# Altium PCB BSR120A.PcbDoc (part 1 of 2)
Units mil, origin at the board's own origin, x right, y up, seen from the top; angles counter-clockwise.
Board outline 3250 x 2500 mil, 4 copper layers (Top Layer, MidLayer1, MidLayer2, Bottom Layer), stack 61.2 mil thick; 56 components, 15 nets, 102 pads, 73 vias.
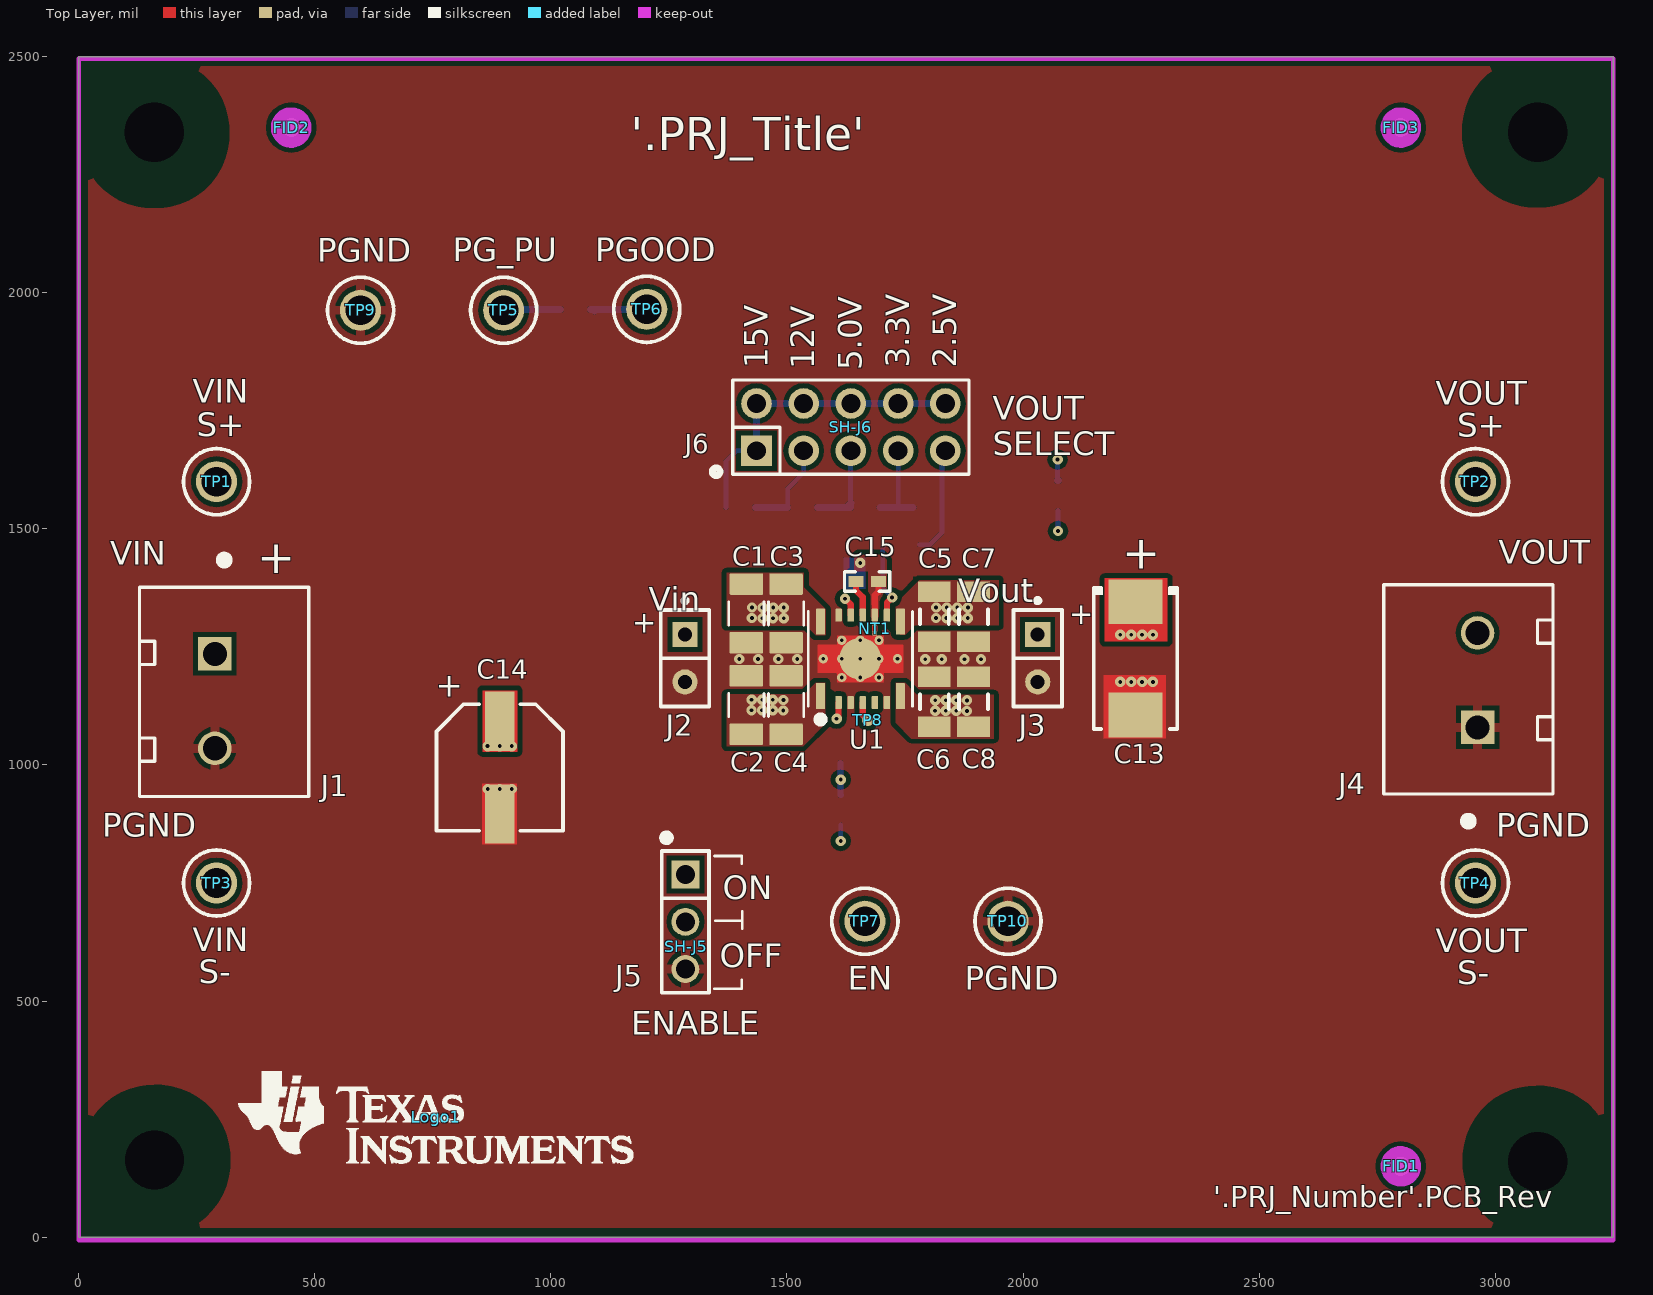
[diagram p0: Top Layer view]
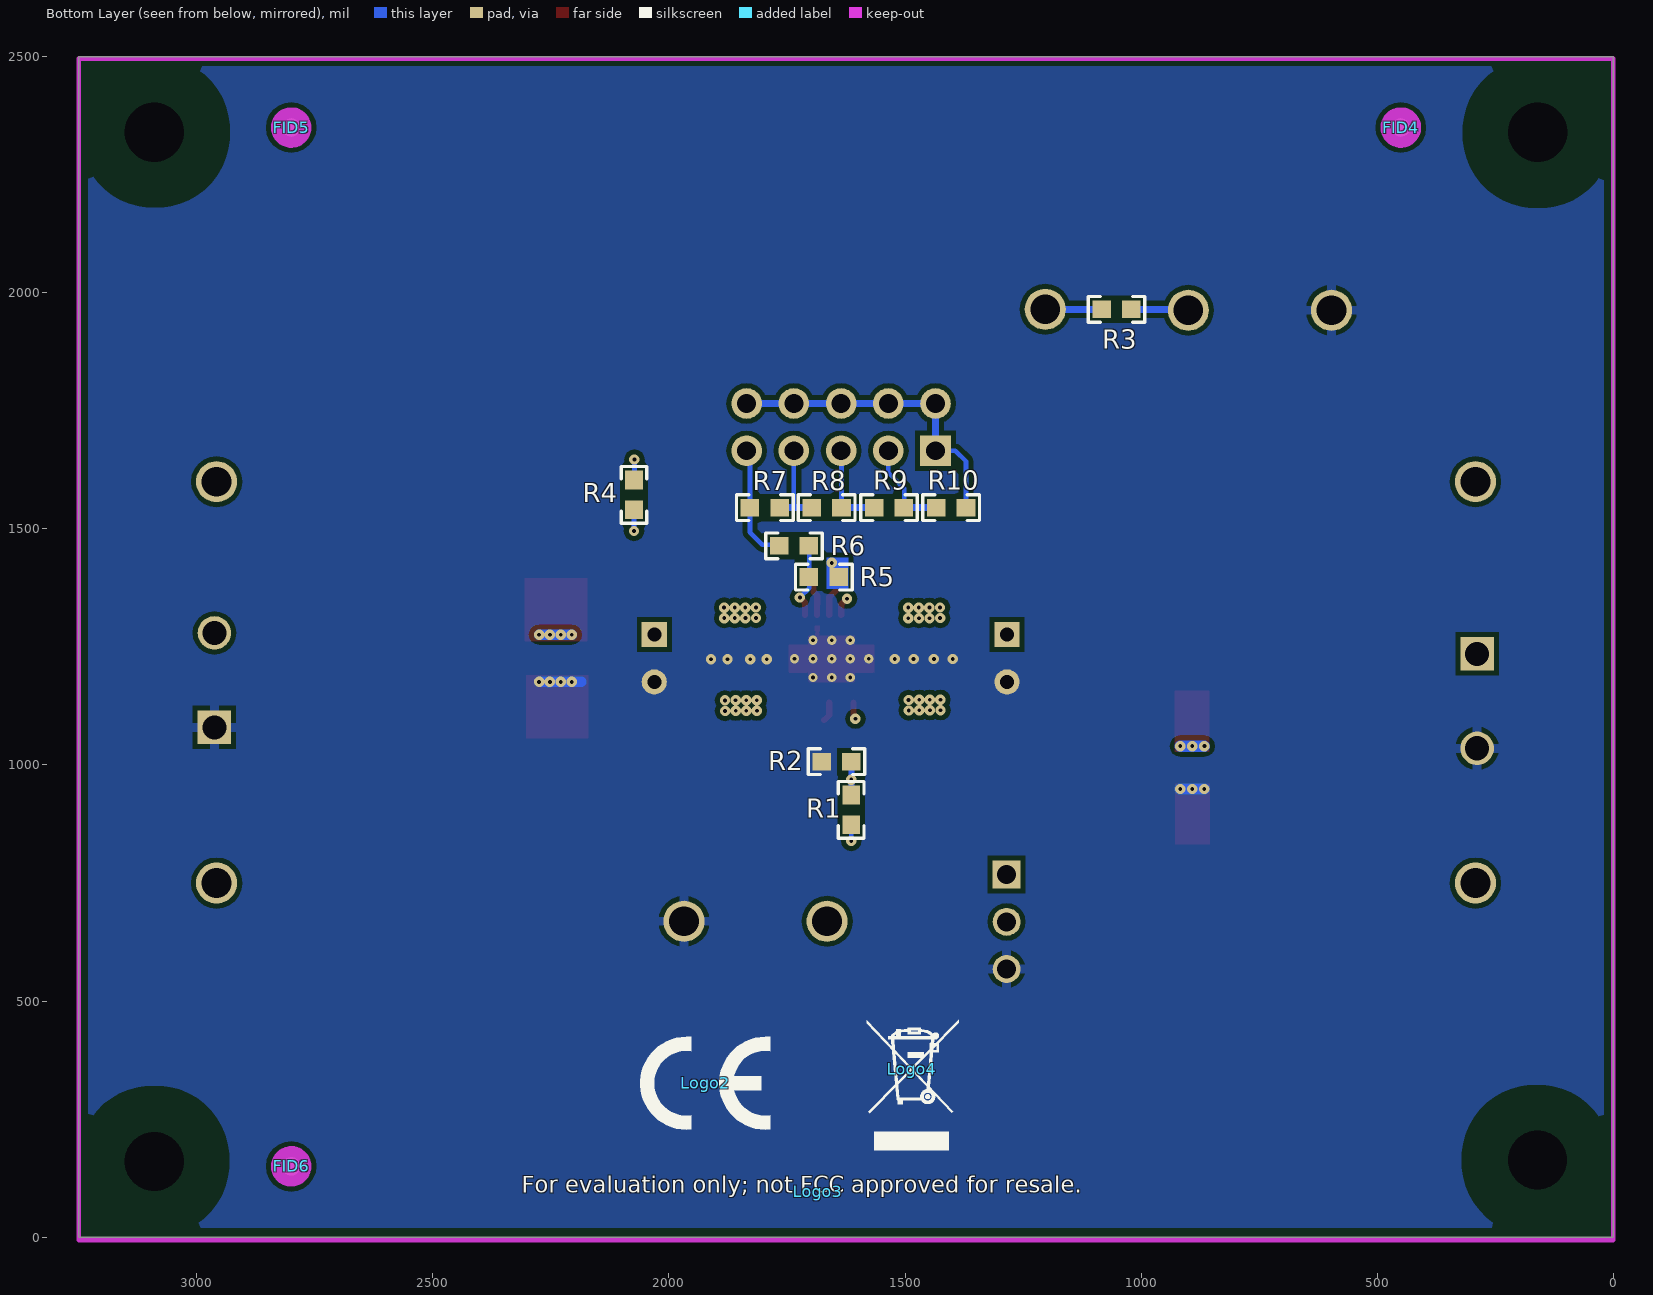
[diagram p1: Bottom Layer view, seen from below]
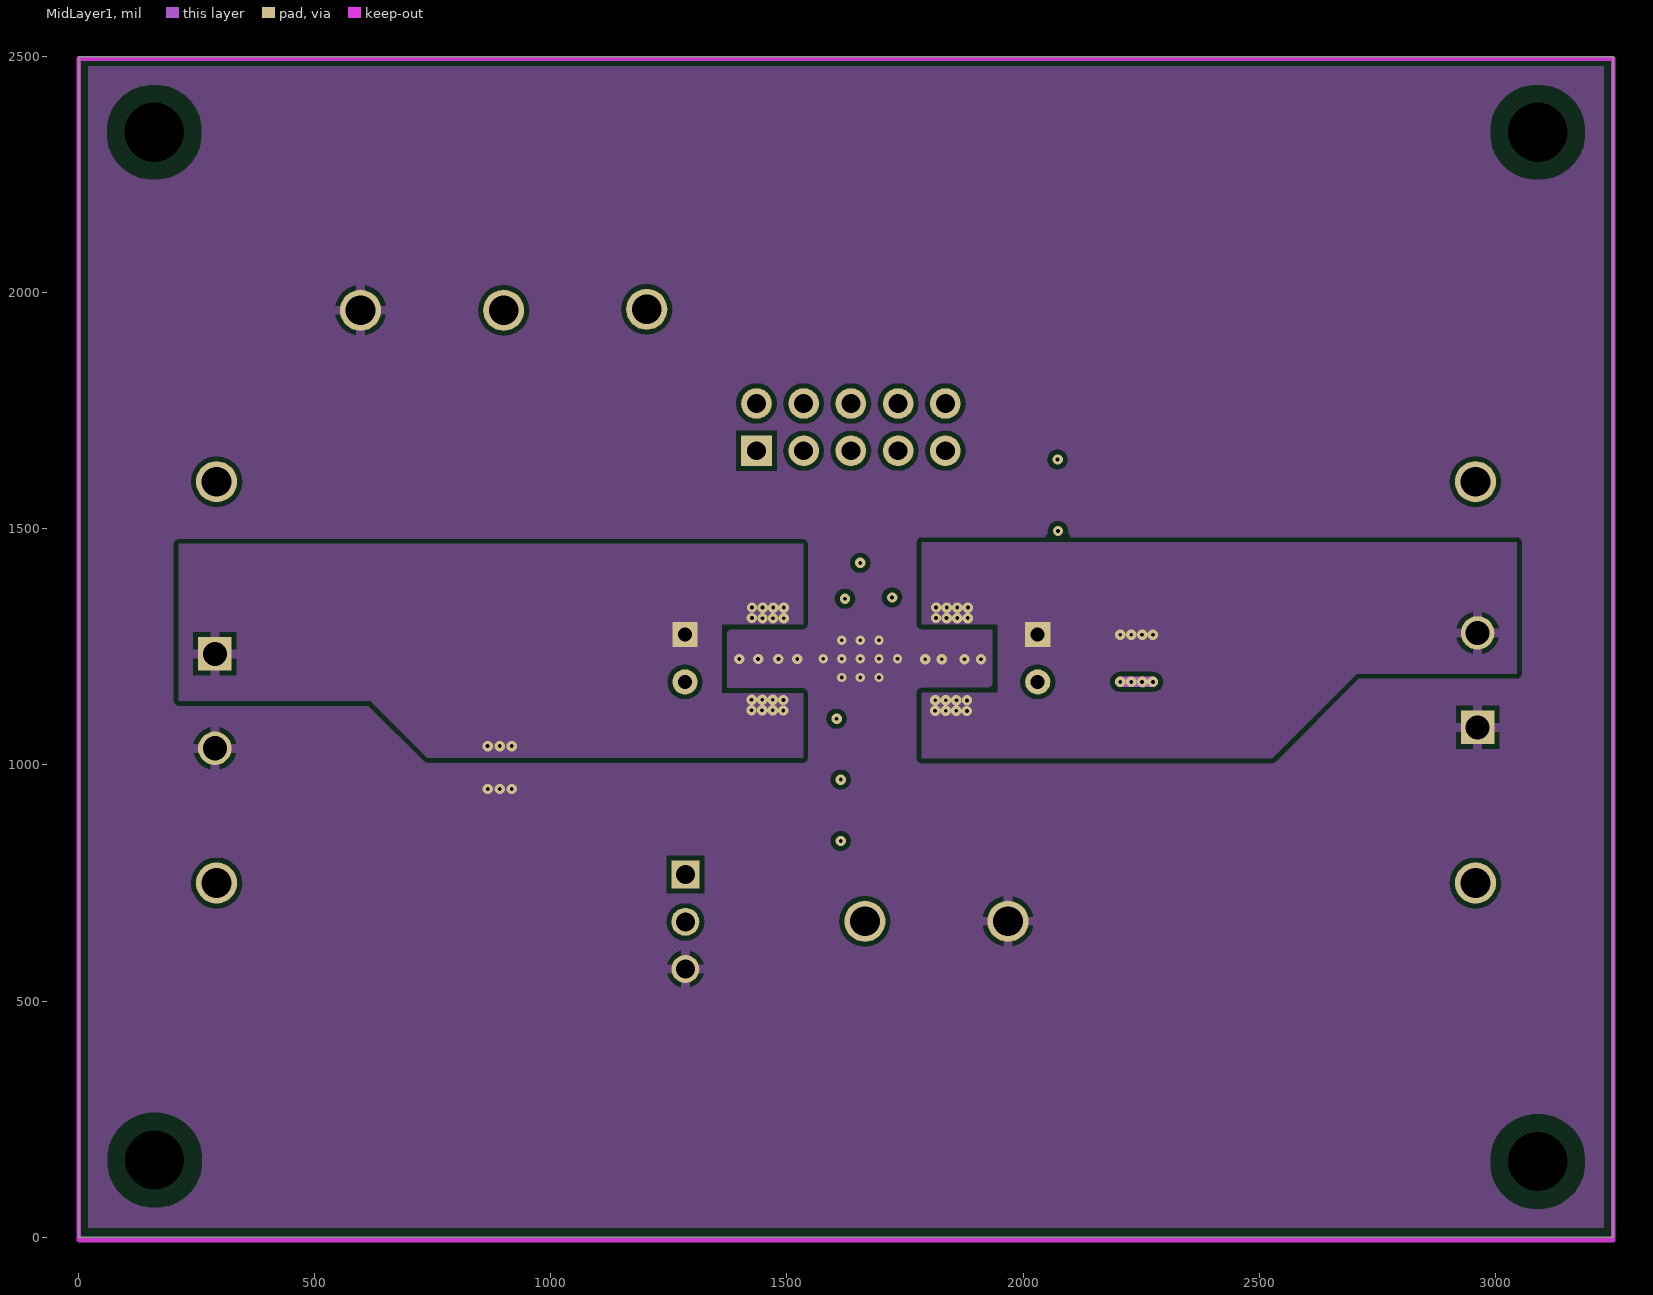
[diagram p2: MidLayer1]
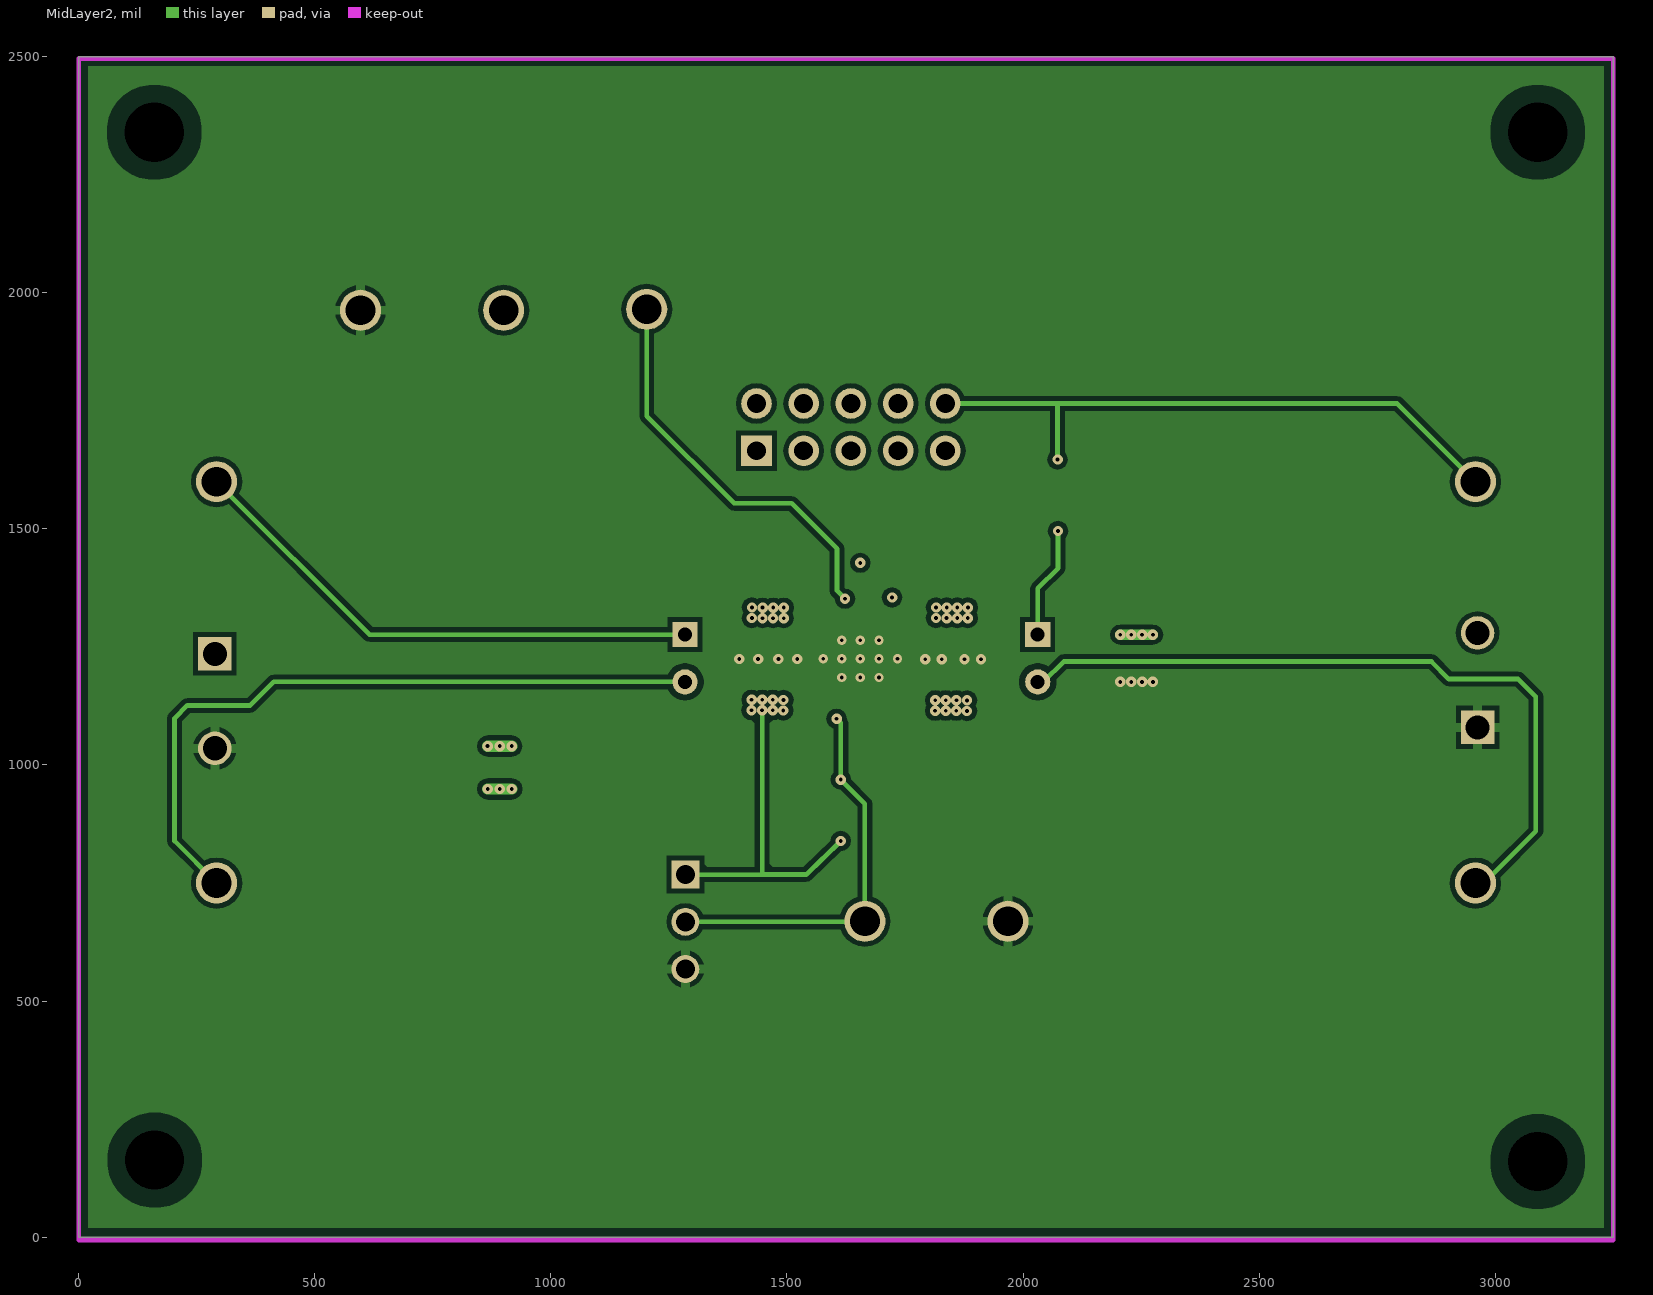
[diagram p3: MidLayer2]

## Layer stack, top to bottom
Top Solder: solder mask 0.4, Solder Resist, Dk 3.5
Top Layer: signal copper 2.8
Dielectric1: prepreg 5, FR-4 High Tg, Dk 4.2
MidLayer1: signal copper 2.8
Dielectric2: core 40, FR-4 High Tg, Dk 4.2
MidLayer2: signal copper 2.8
Dielectric3: prepreg 5, FR-4 High Tg, Dk 4.2
Bottom Layer: signal copper 2.8
Bottom Solder: solder mask 0.4, Solder Resist, Dk 3.5

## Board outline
0,0 0,2500 3250,2500 3250,0

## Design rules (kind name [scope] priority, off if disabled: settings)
AcuteAngle [All] p1: minimum=4.50000000000000E+0001 checktracksonly=TRUE
AssemblyTestPointUsage [All] p1: valid=2
BoardOutlineClearance BoardOutlineClearance_MountingHoles [OnCopper and InComponentClass('Mounting Holes')] p1: gap=40 ignorepadtopadclearanceinfootprint=FALSE
BoardOutlineClearance BoardOutlineClearance_Poly [OnCopper and IsPoly] p2: gap=20 ignorepadtopadclearanceinfootprint=FALSE
BoardOutlineClearance [OnCopper and Not InComponentClass('Logo') and not InComponentClass('FiducialMark') and not InRegion(1000,500,4000,800) and not InPoly] p3: gap=20 ignorepadtopadclearanceinfootprint=FALSE
Clearance Clearance_Keepouts [((IsTrack Or IsArc) And Not InPoly) And IsFree and IsKeepOut vs ((IsTrack Or IsArc) And Not InPoly) And IsFree and IsKeepOut] p1: gap=0 ignorepadtopadclearanceinfootprint=FALSE
Clearance Clearance_Poly [InPolygon] p2: gap=10 ignorepadtopadclearanceinfootprint=FALSE except(0: Arc-Hole Track-Hole SMDPad-Hole THPad-Hole Via-Hole Fill-Hole Poly-Hole Region-Hole Text-Hole)
Clearance Clearance_FiducialMark [IsKeepOut and InComponentClass('FiducialMark') vs IsPad and InComponentClass('FiducialMark')] p3: gap=0 ignorepadtopadclearanceinfootprint=FALSE
Clearance [All] p4: gap=10 ignorepadtopadclearanceinfootprint=FALSE except(0: Arc-Hole Track-Hole SMDPad-Hole THPad-Hole Via-Hole Fill-Hole Poly-Hole Region-Hole Text-Hole)
ComponentClearance ComponentClearance_MountingHoles_FiducialMarks [InComponentClass('Mounting Holes') vs InComponentClass('FiducialMark')] p1: gap=10 collisioncheckmode=3 verticalgap=10 showdistances=FALSE
ComponentClearance ComponentClearance_Shunt [InComponentClass('Header') vs InComponentClass('Shunt')] p2: gap=0 collisioncheckmode=3 verticalgap=0 showdistances=FALSE
ComponentClearance ComponentClearance_Logo [InComponentClass('Logo')] p3: gap=10 collisioncheckmode=3 verticalgap=10 showdistances=FALSE
ComponentClearance ComponentClearance_ScrewToNut [(HasFootprint('NY PMS 440 0025 PH')) vs (HasFootprint('Keystone_1902C'))] p4: gap=5 collisioncheckmode=3 verticalgap=10 showdistances=FALSE
ComponentClearance ComponentClearance_MountingHoles [InComponentClass('Mounting Holes')] p5: gap=10 collisioncheckmode=3 verticalgap=100000 showdistances=FALSE
ComponentClearance ComponentClearance_SmallPassives [HasFootprint('0201*') or HasFootprint('0402*') or HasFootprint('0508') or HasFootprint('0603*') or HasFootprint('0612') or HasFootprint('0805*') or HasFootprint('0815*') or HasFootprint('0830*') or HasFootprint('1206*') or HasFootprint('1210*') or HasFootprint('1808*') or HasFootprint('1812*') or HasFootprint('1825*') or HasFootprint('2010*') or HasFootprint('2220*') or HasFootprint('2225*') or HasFootprint('2512*') or HasFootprint('2728*') or HasFootprint('3518*') vs HasFootprint('0201*') or HasFootprint('0402*') or HasFootprint('0508') or HasFootprint('0603*') or HasFootprint('0612') or HasFootprint('0805*') or HasFootprint('0815*') or HasFootprint('0830*') or HasFootprint('1206*') or HasFootprint('1210*') or HasFootprint('1808*') or HasFootprint('1812*') or HasFootprint('1825*') or HasFootprint('2010*') or HasFootprint('2220*') or HasFootprint('2225*') or HasFootprint('2512*') or HasFootprint('2728*') or HasFootprint('3518*')] p6: gap=8 collisioncheckmode=3 verticalgap=8 showdistances=FALSE
ComponentClearance ComponentClearance_THtoSMT [IsThruComponent vs IsSMTComponent] p7: gap=10 collisioncheckmode=3 verticalgap=30 showdistances=FALSE
ComponentClearance ComponentClearance_THtoTH [IsThruComponent vs IsThruComponent] p8: gap=10 collisioncheckmode=3 verticalgap=30 showdistances=FALSE
ComponentClearance "ComponentClearance_U1 to NT1" [InComponent('NT1') vs InComponent('U1')] p9: gap=0 collisioncheckmode=3 verticalgap=0 showdistances=FALSE
ComponentClearance [All] p10: gap=10 collisioncheckmode=3 verticalgap=30 showdistances=FALSE
DiffPairsRouting [All] p1: maxlimit=100 minlimit=10 mostfreqgap=10 toplayer_minwidth=15 toplayer_maxwidth=15 toplayer_prefwidth=15 midlayer1_minwidth=15 midlayer1_maxwidth=15 midlayer1_prefwidth=15 midlayer2_minwidth=15 midlayer2_maxwidth=15 midlayer2_prefwidth=15 bottomlayer_minwidth=15 bottomlayer_maxwidth=15 bottomlayer_prefwidth=15 maxuncoupledlength=1000
FabricationTestPointUsage TestPointUsage [All] p1: valid=2 allowmultiple=FALSE
FabricationTestpoint Testpoint [All] p1: side=3 testpointundercomponent=TRUE minsize=40 maxsize=100 preferedsize=60 minholesize=0 maxholesize=40 preferedholesize=32 testpointgrid=1 allowsidetop=TRUE allowsidebottom=TRUE usegrid=TRUE gridtolerance=0.01
FanoutControl Fanout_LCC [IsLCC] p1: bgadir=Out bgaviamode=Centered fanoutstyle=Auto fanoutdirection=Alternating viagrid=1 // Fanout_LCC (Default Rule)
FanoutControl Fanout_BGA [IsBGA] p2: bgadir=Out bgaviamode=Centered fanoutstyle=Auto fanoutdirection=Alternating viagrid=1 // Fanout_BGA (Default Rule)
FanoutControl Fanout_Default [All] p4: bgadir=Out bgaviamode=Centered fanoutstyle=Auto fanoutdirection=Alternating viagrid=1 // Fanout_Default (Default Rule)
FanoutControl Fanout_Small [(CompPinCount < 5)] p5: bgadir=Out bgaviamode=Centered fanoutstyle=Auto fanoutdirection=OutThenIn viagrid=1 // Fanout_Small (Default Rule)
Height [All] p1: minheight=0 maxheight=10000 prefheight=500
HoleSize [All] p1: absolutevalues=TRUE maxlimit=251 minlimit=6 maxpercent=80.000 minpercent=20.000
MinimumAnnularRing MinimumAnnularRing_ThermalPadVias [IsVia and InAnyComponent] p1: minimumring=5
MinimumAnnularRing [All] p2: minimumring=5
MinimumSolderMaskSliver MinimumSolderMaskSliver_1 [HasFootprint('RDA0015A-MFG') vs (InComponent('U1') AND IsVia)] p1: minsoldermaskwidth=1
MinimumSolderMaskSliver MinimumSolderMaskSliver_Logo [InComponentClass('Logo') vs InComponentClass('Logo')] p2: minsoldermaskwidth=0.7
MinimumSolderMaskSliver [All] p3: minsoldermaskwidth=3.94
PlaneClearance PlaneClearance_1 [OnLayer('Top Layer')] p1: clearance=7.87
PlaneClearance [All] p2: clearance=9.84
PlaneConnect PlaneConnect_via [IsVia] p1: planeconnectstyle=Direct reliefexpansion=20 reliefentries=4 reliefconductorwidth=10 reliefairgap=10
PlaneConnect [All] p2: planeconnectstyle=Relief reliefexpansion=10 reliefentries=4 reliefconductorwidth=10 reliefairgap=10
PolygonConnect PolygonConnect_ESD120 [HasFootprint('On-Shore_ED120_2DS')] p1: connectstyle=Relief reliefconductorwidth=25 reliefentries=4 polygonreliefangle="90 Angle" airgapwidth=10
PolygonConnect PolygonConnect_tp [(InComponent('TP*') and not (InComponent('TP9') or InComponent('TP10')))] p2: connectstyle=NoConnect reliefconductorwidth=25 reliefentries=4 polygonreliefangle="90 Angle" airgapwidth=10
PolygonConnect PolygonConnect_logo [InComponent('Logo1')] p3: connectstyle=Direct reliefconductorwidth=10 reliefentries=4 polygonreliefangle="90 Angle" airgapwidth=10
PolygonConnect PolygonConnect_Via [IsVia] p4: connectstyle=Direct reliefconductorwidth=10 reliefentries=4 polygonreliefangle="90 Angle" airgapwidth=10
PolygonConnect PolygonConnect_1 [IsThruPin AND NOT (InComponent('J3') or InComponent('J2'))] p5: connectstyle=Relief reliefconductorwidth=20 reliefentries=4 polygonreliefangle="90 Angle" airgapwidth=10
PolygonConnect PolygonConnect_poly [IsPoly] p6: connectstyle=Direct reliefconductorwidth=10 reliefentries=4 polygonreliefangle="90 Angle" airgapwidth=8
PolygonConnect [All] p7: connectstyle=Relief reliefconductorwidth=10 reliefentries=4 polygonreliefangle="90 Angle" airgapwidth=8
RoutingVias ThermalPadVias [IsVia and InAnyComponent] p1: holewidth=7.87 width=19.68 viastyle="Through Hole" minholewidth=7.87 minwidth=19.68 maxholewidth=12.99 maxwidth=23.62
RoutingVias [All] p2: holewidth=16 width=34 viastyle="Through Hole" minholewidth=6 minwidth=19 maxholewidth=40 maxwidth=65
SilkToBoardRegionClearance SilkToBoardRegionClearance_1 [All] p1:
SilkToSilkClearance SilkToSilkClearance_Pb-FreeLogo [(HasFootprint('Pb-Free_Overlay_Medium') OR HasFootprint('Pb-Free_Overlay_Small')) vs (HasFootprint('Pb-Free_Overlay_Medium') OR HasFootprint('Pb-Free_Overlay_Small'))] p1: silktosilkclearance=0
SilkToSilkClearance [All] p2: silktosilkclearance=3
SilkToSolderMaskClearance "Cap silkscreen on vias" [IsTrack and (InComponent('C1') or InComponent('C11') or InComponent('C12') or InComponent('C2')or InComponent('C5') or InComponent('C6') or InComponent('C7') or InComponent('C8') or InComponent('C13') or InComponent('C14') or InComponent('C15') or InComponent('C16') or InComponent('C11') or InComponent('C12') or InComponent('C3') or InComponent('C4') or InComponent('R1') or InComponent('R2') or InComponent('U1')) vs IsVia] p1: minsilkscreentomaskgap=0 clearancetoexposedcopper=FALSE
SilkToSolderMaskClearance SilkToComponentPadClearance [(IsPad or IsFill or IsRegion) and InAnycomponent] p2: minsilkscreentomaskgap=4.8 clearancetoexposedcopper=TRUE
SilkToSolderMaskClearance "Silk to Solder Mask Opening" [All] p3: minsilkscreentomaskgap=4 clearancetoexposedcopper=FALSE
SolderMaskExpansion [All] p1: expansion=1.97
Width [All] p1: maxlimit=100 minlimit=6 preferedwidth=10 checkconnectedcopper=TRUE
13 further rules are at their usual default settings.

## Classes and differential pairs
component class Shunt: SH-J5 SH-J6
component class Header: J5 J6
component class AssemblyNote: ZZ1 ZZ2 ZZ3 ZZ4 ZZ5
component class FiducialMark: FID1 FID2 FID3 FID4 FID5 FID6
component class Logo: Logo1
component class BSR120A_Hardware: !PCB FID1 FID2 FID3 FID4 FID5 FID6 Logo1 Logo2 Logo3 Logo4 SH-J5 SH-J6 ZZ1 ZZ2 ZZ3 ZZ4 ZZ5
component class BSR120A: C1 C2 C3 C4 C5 C6 C7 C8 C13 C14 C15 J1 J2 J3 J4 J5 J6 NT1 R1 R2 R3 R4 R5 R6 R7 R8 R9 R10 TP1 TP2 TP3 TP4 TP5 TP6 TP7 TP8 TP9 TP10 U1

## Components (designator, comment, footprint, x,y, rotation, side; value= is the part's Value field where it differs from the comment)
C1 "GRM31CC72A475KE11L" FP-GRM31CC72A475KE11L_1206-MFG 1414,1321 r90 top value=4.7µF
C2 "GRM31CC72A475KE11L" FP-GRM31CC72A475KE11L_1206-MFG 1414,1127 r270 top value=4.7µF
C3 "GRM31CC72A475KE11L" FP-GRM31CC72A475KE11L_1206-MFG 1498,1321 r90 top value=4.7µF
C4 "GRM31CC72A475KE11L" FP-GRM31CC72A475KE11L_1206-MFG 1498,1127 r270 top value=4.7µF
C5 "C3216X5R1E476M160AC" 1206_190L 1812,1314 r90 top value=47uF
C6 "C3216X5R1E476M160AC" 1206_190L 1812,1134 r270 top value=47uF
C7 "C3216X5R1E476M160AC" 1206_190L 1895,1314 r90 top value=47uF
C8 "C3216X5R1E476M160AC" 1206_190L 1895,1134 r270 top value=47uF
C13 "T520Y337M010ATE035" 7343-40 2238,1226 r270 top value=330uF
C14 "EEEFT1H470AP" Panasonic_D 891.6,994.6 r270 top value=47uF
C15 "EMK105BJ105KVHF" 0402 1669.92,1388.48 r0 top value=1uF
FID1 "Fiducial" Fiducial10-20 2800,150 r0 top
FID2 "Fiducial" Fiducial10-20 450,2350 r0 top
FID3 "Fiducial" Fiducial10-20 2800,2350 r0 top
FID4 "Fiducial" Fiducial10-20 450,2350 r180 bottom
FID5 "Fiducial" Fiducial10-20 2800,2350 r180 bottom
FID6 "Fiducial" Fiducial10-20 2800,150 r180 bottom
J1 "OSTTA024163" On-Shore_OSTTA024163 308,1155 r270 top
J2 "310-43-102-41-001000" Mill-max_310-43-102-41-001000 1284,1226 r270 top
J3 "310-43-102-41-001000" Mill-max_310-43-102-41-001000 2031,1226 r270 top
J4 "OSTTA024163" On-Shore_OSTTA024163 2943,1160 r90 top
J5 "PEC03SAAN" CONN_PEC03SAAN 1284.74,667.8 r270 top
J6 "PEC05DAAN" CONN_PEC05DAAN 1635.4,1715.5 r0 top
Logo1 "Texas Instruments" TI_Stacked_Overlay_Small 756.39,253.53 r0 top
Logo2 "CE Mark" CE_Mark_5mm 1923,326 r180 bottom
Logo3 "FCC disclaimer" FCC_disclaimer 1685,96 r180 bottom
Logo4 "WEEE logo" WEEE_Minimum 1486,356 r180 bottom
NT1 "Net-Tie" Net-Tie_10mil 1686,1289 r270 top net-tie
R1 "CRCW0603402KFKEA" 0603 1614,905 r270 bottom value=402k
R2 "CRCW0603133KFKEA" 0603 1645,1007 r180 bottom value=133k
R3 "CRCW060349K9FKEA" 0603 1052,1965 r0 bottom value=49.9k
R4 "CRCW060320R0JNEA" 0603 2074,1572 r90 bottom value=20
R5 "CRCW060310K0FKEA" 0603 1672,1398 r0 bottom value=10.0k
R6 "CRCW060315K0FKEA" 0603 1735,1464 r0 bottom value=15.0k
R7 "CRCW06038K06FKEA" 0603 1797,1545 r180 bottom value=8.06k
R8 "CRCW060316K9FKEA" 0603 1666,1545 r180 bottom value=16.9k
R9 "CRCW060369K8FKEA" 0603 1534,1545 r180 bottom value=69.8k
R10 "CRCW060330K1FKEA" 0603 1402.4,1545 r180 bottom value=30.1k
SH-J5 "2SN-BK-G" 2SN-BK-G 1287,615 r90 top value=1x2
SH-J6 "2SN-BK-G" 2SN-BK-G 1635.4,1715.5 r90 top value=1x2
TP1 "5010" Keystone5010 292,1600 r90 top
TP2 "5010" Keystone5010 2958,1600 r90 top
TP3 "5011" Keystone5011 292,750 r90 top
TP4 "5011" Keystone5011 2958,750 r90 top
TP5 "5012" Keystone5012 900,1963 r0 top
TP6 "5012" Keystone5012 1203,1965 r0 top
TP7 "5012" Keystone5012 1665,669 r0 top
TP8 "TESTPOINT" TP_25MIL-SMT 1671,1095 r0 top
TP9 "5011" Keystone5011 597,1963 r180 top
TP10 "5011" Keystone5011 1968,669 r0 top
U1 "TPSM5601R5H" RDA0015A-MFG 1655.45,1224.74 r90 top
ZZ1 "These assemblies are ESD sensitive, ESD precautions shall be observed." AssemblyNote -430,3004 r0 top
ZZ2 "These assemblies must be clean and free from flux and all contaminants. Use of no clean flux is not acceptable." AssemblyNote -430,3188 r0 top
ZZ3 "These assemblies must comply with workmanship standards IPC-A-610 Class 2, unless otherwise specified." AssemblyNote -430,3371 r0 top
ZZ4 "Place SH-J5 on J5 pins 2 and 3" AssemblyNote -425,3544 r0 top
ZZ5 "Place SH-J6 on J6 pins 5 and 6" AssemblyNote -434,3678 r0 top

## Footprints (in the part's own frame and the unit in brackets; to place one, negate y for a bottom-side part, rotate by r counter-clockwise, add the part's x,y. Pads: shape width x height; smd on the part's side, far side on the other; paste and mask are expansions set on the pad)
2SN-BK-G [mil] "Samtec STEP model"
  round 1 on Mech3: 0(0,0)
  body extent -78,-39 79,39, height 188
0402 [mm] "0402 from SM-752 data"
  rect 0.8x0.6 smd: 1(-0.6,0) 2(0.6,0)
  silkscreen extent -1.22,-0.52 1.22,0.52, body extent -0.55,-0.3 0.55,0.3, height 0.6
0603 [mm] "0603 from SM-752 data"
  rect 1x0.95 smd: 1(-0.8,0) 2(0.8,0)
  silkscreen extent -1.52,-0.69 1.52,0.69, body extent -0.87,-0.47 0.87,0.47, height 1
1206_190L [mm] "1206_190"
  rect 1.1x1.75 smd: 1(-1.35,0) 2(1.35,0)
  silkscreen extent -0.4,-0.77 0.4,0.77, body extent -1.75,-0.95 1.75,0.95, height 1.9
7343-40 [mm] "Molded, 2-Leads, Body 7.3x4.3mm, Height 4mm"
  rect 2.4x2.9 smd: 1(-3.05,0) 2(3.05,0)
  silkscreen extent -3.8,-2.25 3.8,2.25, body extent -3.8,-2.25 3.8,2.25, height 4.01
AssemblyNote [mil] "Assembly Note"
CE_Mark_5mm [mil] "Minimum text height for CE Mark"
  silkscreen extent -138,-98 138,98
CONN_PEC03SAAN [mm] "SULLINS"
  rect 1.5x1.5 hole 1.016: 1(-2.54,0)
  round 1.5 hole 1.016: 2(0,0) 3(2.54,0)
  silkscreen extent -4.72,-1.27 3.81,1.27, body extent -3.84,-1.3 3.84,1.3, height 8.38
CONN_PEC05DAAN [mm] "SULLINS"
  rect 1.65x1.65 hole 1.016 mask+0: 1(-5.08,-1.27)
  round 1.65 hole 1.016 mask+0: 2(-5.08,1.27) 3(-2.54,-1.27) 4(-2.54,1.27) 5(0,-1.27) 6(0,1.27) 7(2.54,-1.27) 8(2.54,1.27) 9(5.08,-1.27) 10(5.08,1.27)
  silkscreen extent -7.45,-2.6 6.35,2.54, body extent -6.35,-2.54 6.35,2.54, height 8.38
FCC_disclaimer [mil]
Fiducial10-20 [mm]
  round 1 smd mask+0.5: 1(0,0)
  Top Layer keep-out circle w1.178: c0,0 r0.5
FP-GRM31CC72A475KE11L_1206-MFG [mm]
  rrect9% 1.15x1.8 smd paste+0 mask+0: 1(-1.575,0) 2(1.575,0)
  silkscreen extent -0.63,-0.95 0.63,0.95, body extent -2.25,-1.05 2.25,1.05, height 0.25
Keystone5010 [mil] "Keystone Multipurpose loops"
  round 87 hole 63: 1(0,0)
  silkscreen extent -70,-70 70,70, body extent -63,-63 63,62, height 319
Keystone5011 [mil] "Keystone Multipurpose loops"
  round 87 hole 63: 1(0,0)
  silkscreen extent -70,-70 70,70, body extent -63,-63 63,62, height 319
Keystone5012 [mil] "Keystone Multipurpose loops"
  round 87 hole 63: 1(0,0)
  silkscreen extent -70,-70 70,70, body extent -63,-63 63,62, height 319
Mill-max_310-43-102-41-001000 [mm] "Mill-max"
  rect 1.35x1.35 hole 0.75: 1(-1.27,0)
  round 1.35 hole 0.75: 2(1.27,0)
  silkscreen extent -3.22,-1.3 2.6,1.3, body extent -2.55,-1.27 2.55,1.27, height 4.22
Net-Tie_10mil [mil] "10mil net tie, no solder mask opening, no solder paste"
  rect 10x10 smd paste-5 mask-5: 1(-10,0) 2(10,0)
  Top Layer region: -6,5 6,5 6,-5 -6,-5
On-Shore_OSTTA024163 [mm] "TERM BLOCK 2x1, 5.08mm, TH"
  rect 1.8x1.8 hole 1.3: 1(-2.04,-0.5)
  round 1.8 hole 1.3 paste+0: 2(3.04,-0.5)
  silkscreen extent -7.18,-4.55 5.63,4.55, body extent -5.68,-4.6 5.68,4.6, height 13
Panasonic_D [mm] "SMD, 2-Leads, Dia 6.3mm"
  rect 3.2x1.6 smd: 1(-2.5,0) 2(2.5,0)
  silkscreen extent -3.4,-3.4 3.4,3.4, body extent -3.4,-3.4 3.4,3.4, height 6.11
RDA0015A-MFG [mm]
  rrect20% 1.4x0.5 smd paste-1000 mask+0: 1(-2,2.145) 7(-2,-2.155) 8(2,-2.155) 14(2,2.145)
  rrect29% 0.7x0.35 smd paste-1000 mask+0: 2(-2.35,1.17) 3(-2.35,0.52) 4(-2.35,-0.13) 5(-2.35,-0.78) 6(-2.35,-1.43) 9(2.35,-1.43) 10(2.35,-0.78) 11(2.35,-0.13) 12(2.35,0.52) 13(2.35,1.17)
  round 2.25 smd paste-1000 mask+0: 15(0,0)
  Top Layer region: -0.7,2.3 -0.725,2.293 -0.743,2.275 -0.75,2.25 -0.75,2.25 -0.75,1.3 -0.754,1.281 -0.765,1.265 -0.781,1.254 -0.8,1.25 -0.8,1.25 -1.2,1.25 -1.225,1.243 -1.243,1.225 -1.25,1.2 -1.25,1.2 -1.25,-1.2 -1.243,-1.225 -1.225,-1.243 -1.2,-1.25 -1.2,-1.25 -0.8,-1.25 -0.781,-1.254 -0.765,-1.265 -0.754,-1.281 -0.75,-1.3 -0.75,-1.3 -0.75,-2.25 -0.743,-2.275 -0.725,-2.293 -0.7,-2.3 -0.7,-2.3 0.7,-2.3 0.725,-2.293 0.743,-2.275 0.75,-2.25 0.75,-2.25 0.75,-1.3 0.754,-1.281 0.765,-1.265 0.781,-1.254 0.8,-1.25 0.8,-1.25 1.2,-1.25 1.225,-1.243 1.243,-1.225 1.25,-1.2 1.25,-1.2 1.25,1.2 1.243,1.225 1.225,1.243 1.2,1.25 1.2,1.25 0.8,1.25 0.781,1.254 0.765,1.265 0.754,1.281 0.75,1.3 0.75,1.3 0.75,2.25 0.743,2.275 0.725,2.293 0.7,2.3 0.7,2.3
  silkscreen extent -3.47,-2.8 2.55,2.8, body extent -2.8,-2.9 2.8,2.9, height 0.25
TI_Stacked_Overlay_Small [mil]
  silkscreen extent -418,-98 418,98
TP_25MIL-SMT [mil]
  round 25 smd mask-2.5: 1(0,0)
WEEE_Minimum [mil] "WEEElie bin"
  silkscreen extent -95,-172 99,104

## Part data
C1 C2 C3 C4: library part CMP-0089881-1, "4.7µF ±10% 100V Ceramic Capacitor X7S 1206 (3216 Metric)", Digikey Part Number=490-18620-1-ND, Manufacturer=Murata, Mouser Part Number=81-GRM31CC72A475KE1L, Operating Temperature Range="-55°C to +125°C", TempCo=22%, Temperature Characteristic=X7S, Tolerance_%=10%, ValueDisplayed=4.7uF
C5 C6 C7 C8: library part CMP-0008656-2, "CAP, CERM, 47 uF, 25 V, +/- 20%, X5R, 1206_190", Cap_Case=1206, Manufacturer=TDK, Supplier Part Number 1=445-8047-1-ND, TempCo=X5R, Tolerance_%=20%, Value1=Unknown, Value2=25V, ValueDisplayed=47uF
C13: library part CMP-0064986-2, "CAP, Tantalum Polymer, 330 uF, 10 V,+/- 20%, 0.035 ohm, 7343-40 SMD", Cap_Case=7343-40, Manufacturer=Kemet, Supplier Part Number 1=399-10363-1-ND, Tolerance_%=20%, Value1="0.035 ohm", Value2=10V, ValueDisplayed=330uF
C14: library part CMP-0011204-2, "CAP, AL, 47 uF, 50 V, +/- 20%, 0.68 ohm, AEC-Q200 Grade 2, SMD", Cap_Case=6.3x5.8mm, Manufacturer=Panasonic, Supplier Part Number 1=PCE5023CT-ND, Tolerance_%=20%, Value1="0.68 ohm", Value2=50V, ValueDisplayed=47uF
C15: library part CMP-0006347-2, "CAP, CERM, 1 uF, 16 V, +/- 10%, X5R, 0402", Cap_Case=0402, Manufacturer="Taiyo Yuden", Supplier Part Number 1=587-3709-2-ND, TempCo=X5R, Tolerance_%=10%, Value1=Unknown, Value2=16V, ValueDisplayed=1uF
FID1 FID2 FID3 FID4 FID5 FID6: library part CMP-0077181-1, "Fiducial mark.  There is nothing to buy or mount.", Manufacturer=N/A
J1 J4: library part CMP-0074959-1, "Terminal Block, 2x1, 5.08mm, TH", Manufacturer="On-Shore Technology", Supplier Part Number 1=ED2580-ND
J2 J3: library part CMP-0055017-1, "Socket Strip, 2x1, 100mil, Black, Tin, TH", Manufacturer=Mill-Max, Supplier Part Number 1=ED6202-ND
J5: library part CMP-0002338-1, "Header, 100mil, 3x1, Tin, TH", Color=Black, Current_A=3A, Manufacturer="Sullins Connector Solutions", Supplier Part Number 1=S1012E-03-ND, Voltage_V=1.8kV
J6: library part CMP-0054550-2, "Header, 100mil, 5x2, Tin, TH", Color=Black, Current_A=3A, Manufacturer="Sullins Connector Solutions", Supplier Part Number 1=S2012E-05-ND, Voltage_V=1.8kV
Logo1: library part CMP-0074838-1, "Texas Instrument Corporate Signature"
Logo2: library part CMP-0074844-1
Logo3: library part CMP-0074847-1, "FCC_disclaimer"
Logo4: library part CMP-0074769-1
NT1: library part CMP-0078142-3, "Single point connection between nets.", Manufacturer=N/A
R1: library part CMP-0022408-4, "RES, 402 k, 1%, 0.1 W, AEC-Q200 Grade 0, 0603", Manufacturer=Vishay-Dale, Power_W=100mW, Supplier Part Number 1=541-402KHCT-ND, TempCo="100 ppm/C", Tolerance_%=1%, Value2=0.1W, Value_Code=402k
R2: library part CMP-0022038-4, "RES, 133 k, 1%, 0.1 W, AEC-Q200 Grade 0, 0603", Manufacturer=Vishay-Dale, Power_W=100mW, Supplier Part Number 1=541-133KHCT-ND, TempCo="100 ppm/C", Tolerance_%=1%, Value2=0.1W, Value_Code=133k
R3: library part CMP-0022447-4, "RES, 49.9 k, 1%, 0.1 W, AEC-Q200 Grade 0, 0603", Manufacturer=Vishay-Dale, Power_W=100mW, Supplier Part Number 1=541-49.9KHCT-ND, TempCo="100 ppm/C", Tolerance_%=1%, Value2=0.1W, Value_Code=49k9, ValueDisplayed=49.9k
R4: library part CMP-0025754-4, "RES, 20, 5%, 0.1 W, AEC-Q200 Grade 0, 0603", Manufacturer=Vishay-Dale, Power_W=100mW, Supplier Part Number 1=541-20GCT-ND, TempCo="200 ppm/C", Tolerance_%=5%, Value2=0.1W, Value_Code=20R0, ValueDisplayed=20
R5: library part CMP-0021998-4, "RES, 10.0 k, 1%, 0.1 W, AEC-Q200 Grade 0, 0603", Manufacturer=Vishay-Dale, Power_W=100mW, Supplier Part Number 1=541-10.0KHCT-ND, TempCo="100 ppm/C", Tolerance_%=1%, Value2=0.1W, Value_Code=10k0, ValueDisplayed=10.0k
R6: library part CMP-0022066-4, "RES, 15.0 k, 1%, 0.1 W, AEC-Q200 Grade 0, 0603", Manufacturer=Vishay-Dale, Power_W=100mW, Supplier Part Number 1=541-15.0KHCT-ND, TempCo="100 ppm/C", Tolerance_%=1%, Value2=0.1W, Value_Code=15k0, ValueDisplayed=15.0k
R7: library part CMP-0022634-4, "RES, 8.06 k, 1%, 0.1 W, AEC-Q200 Grade 0, 0603", Manufacturer=Vishay-Dale, Power_W=100mW, Supplier Part Number 1=541-8.06KHCT-ND, TempCo="100 ppm/C", Tolerance_%=1%, Value2=0.1W, Value_Code=8k06, ValueDisplayed=8.06k
R8: library part CMP-0022081-4, "RES, 16.9 k, 1%, 0.1 W, AEC-Q200 Grade 0, 0603", Manufacturer=Vishay-Dale, Power_W=100mW, Supplier Part Number 1=541-16.9KHCT-ND, TempCo="100 ppm/C", Tolerance_%=1%, Value2=0.1W, Value_Code=16k9, ValueDisplayed=16.9k
R9: library part CMP-0022556-4, "RES, 69.8 k, 1%, 0.1 W, AEC-Q200 Grade 0, 0603", Manufacturer=Vishay-Dale, Power_W=100mW, Supplier Part Number 1=541-69.8KHCT-ND, TempCo="100 ppm/C", Tolerance_%=1%, Value2=0.1W, Value_Code=69k8, ValueDisplayed=69.8k
R10: library part CMP-0022324-4, "RES, 30.1 k, 1%, 0.1 W, AEC-Q200 Grade 0, 0603", Manufacturer=Vishay-Dale, Power_W=100mW, Supplier Part Number 1=541-30.1KHCT-ND, TempCo="100 ppm/C", Tolerance_%=1%, Value2=0.1W, Value_Code=30k1, ValueDisplayed=30.1k
SH-J5 SH-J6: library part CMP-0003641-1, "Shunt, 2mm, Gold plated, Black", Manufacturer=Samtec, Supplier Part Number 1=SAM8748-ND
TP1 TP2: library part CMP-0055147-1, "Test Point, Multipurpose, Red, TH", Color=Red, Manufacturer=Keystone, Supplier Part Number 1=36-5010-ND
TP3 TP4 TP9 TP10: library part CMP-0055148-1, "Test Point, Multipurpose, Black, TH", Color=Black, Manufacturer=Keystone, Supplier Part Number 1=36-5011-ND
TP5 TP6 TP7: library part CMP-0055149-1, "Test Point, Multipurpose, White, TH", Color=White, Manufacturer=Keystone, Supplier Part Number 1=36-5012-ND
TP8: library part CMP-0078143-3, "TEST POINT.  No entry in BOM.", Manufacturer=N/A
U1: library part CMP-0088999-2, "60-V Input, 1-V to 16-V Output, 1.5-A Power Module", Manufacturer="Texas Instruments", Max Supply Voltage=60V, Min Supply Voltage=4.2V, Negative Voltage Available=true, Nominal Supply Current=26uA, Operating Temperature Range="-40°C to +125°C", Output Voltage=1-16V, Switching Frequency=1MHz
ZZ1: library part CMP-0077236-1
ZZ2: library part CMP-0077237-1
ZZ3: library part CMP-0077238-1
ZZ4 ZZ5: library part CMP-0003615-1, "This Assembly Note will show in the PcbDoc and associated outputs"

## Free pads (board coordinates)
  round 120 hole 125 unplated: 0(160,2340) 0(161,163) 0(3090,160) 0(3090,2340)

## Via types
v1: diameter 22, hole 8, Top Layer to Bottom Layer, 62 vias
v2: diameter 19.68, hole 7.87, Top Layer to Bottom Layer, 11 vias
